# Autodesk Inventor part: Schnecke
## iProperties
Created: 2008-11
Part Number: Schnecke
Material: Steel, Mild
Document SubType Name: Modeling
Designer: nkrapf
Density: 7.86 g/cm^3
CustomPartVersion: 1
Author: nkrapf
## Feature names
1. Grundkörper [Extrusion]
2. Chamfer1
3. Chamfer2
4. Zahn
5. Zahnanordnung [Circular Pattern]
6. Linker Zahn
7. Linke Zahnanordnung [Circular Pattern]
